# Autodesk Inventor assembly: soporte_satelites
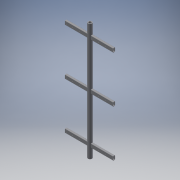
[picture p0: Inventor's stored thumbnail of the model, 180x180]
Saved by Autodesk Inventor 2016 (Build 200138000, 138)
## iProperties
Created: 2016-10
Part Number: soporte_satelites
Document SubType Name: Assembly
Designer: Ingenieria
Author: Ingenieria
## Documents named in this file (3)
- C:\Users\ingenieria\Desktop\Project\soporte_satelites.iam
- C:\Users\ingenieria\Desktop\Project\Eje_principal.ipt
- C:\Users\ingenieria\Desktop\Project\brazo_superior.ipt
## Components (7 placed, 2 different names)
1. Eje_principal:1 — Mate:1, Mate:2, Mate:3, Mate:4, Flush:1, Mate:6, Mate:8, Mate:11, Mate:13, Mate:16
2. brazo_superior:1 — Mate:4, Mate:5, Flush:1, Flush:2, Mate:10
3. brazo_superior:2 — Mate:6, Mate:7, Flush:2
4. brazo_superior:3 — Mate:8, Mate:9, Mate:10, Flush:3, Mate:15
5. brazo_superior:4 — Mate:11, Mate:12, Flush:3
6. brazo_superior:5 — Mate:13, Mate:14, Mate:15, Flush:4
7. brazo_superior:6 — Mate:16, Mate:17, Flush:4
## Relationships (21: Mate 17, Flush 4)
- Mate:1: Eje_principal:1
- Mate:2: Eje_principal:1
- Mate:3: Eje_principal:1
- Mate:4: Eje_principal:1 ↔ brazo_superior:1
- Mate:5: brazo_superior:1
- Flush:1: Eje_principal:1 ↔ brazo_superior:1
- Mate:6: Eje_principal:1 ↔ brazo_superior:2
- Mate:7: brazo_superior:2
- Flush:2: brazo_superior:1 ↔ brazo_superior:2
- Mate:8: Eje_principal:1 ↔ brazo_superior:3
- Mate:9: brazo_superior:3
- Mate:10: brazo_superior:1 ↔ brazo_superior:3
- Mate:11: Eje_principal:1 ↔ brazo_superior:4
- Mate:12: brazo_superior:4
- Flush:3: brazo_superior:3 ↔ brazo_superior:4
- Mate:13: Eje_principal:1 ↔ brazo_superior:5
- Mate:14: brazo_superior:5
- Mate:15: brazo_superior:3 ↔ brazo_superior:5
- Mate:16: Eje_principal:1 ↔ brazo_superior:6
- Mate:17: brazo_superior:6
- Flush:4: brazo_superior:5 ↔ brazo_superior:6
